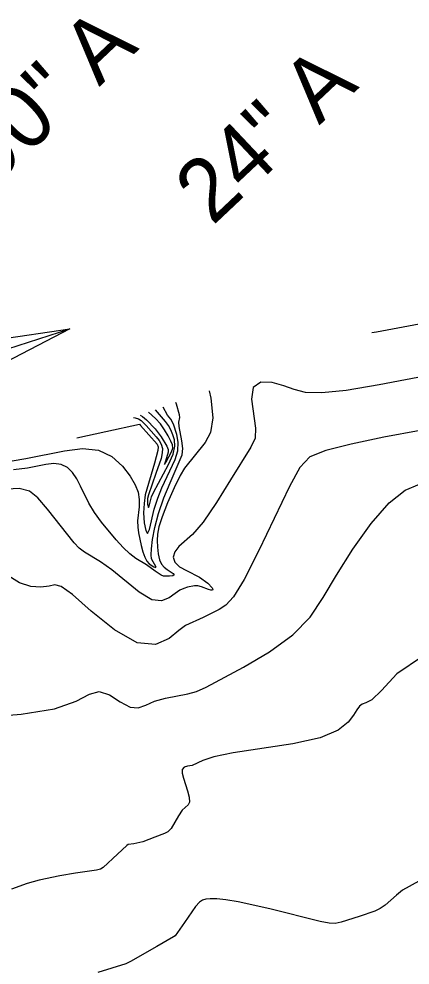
# Model space of a CAD drawing. Extents: x -291892836 to 2945206, y -477993085 to 1832792.
# Drawn here: x 1850179 to 1850412, y 542785 to 543349 of the extents above; entities that cross this region are included whole.
import ezdxf

# ---------------------------------------------------------------- set-up
doc = ezdxf.new("R2010")
doc.units = 0
for name, color, linetype in [('DT_X_Contour_Minor', 7, 'Continuous'), ('Level 31', 7, 'Continuous'), ('Level 40', 7, 'Continuous')]:
    doc.layers.add(name, color=color, linetype=linetype)

msp = doc.modelspace()

# ---------------------------------------------------------------- linework, layer by layer
at = {"layer": 'DT_X_Contour_Minor'}
for points in [[(1850427.18, 543169.02), (1850392.15, 543162.56), (1850389.23, 543162.21)], [(1850445.07, 543140.85), (1850393.64, 543131.12), (1850374.1, 543127.86), (1850359.47, 543126.3), (1850349.69, 543126.66), (1850342.92, 543128.37), (1850336.84, 543130.62), (1850329.84, 543132.51), (1850323.13, 543132.68), (1850318.62, 543129.65), (1850317.59, 543122.63), (1850319.94, 543105.28), (1850319.65, 543099.36), (1850317.22, 543093.98), (1850305.11, 543074.54), (1850296.68, 543061.09), (1850288.66, 543049.35), (1850282.28, 543041.87), (1850274.11, 543034.76), (1850271.79, 543031.72), (1850270.86, 543028.49), (1850271.76, 543025.41), (1850274.64, 543022.77), (1850278.72, 543020.49), (1850286.49, 543016.5), (1850291.44, 543013), (1850294.13, 543010.26), (1850294.55, 543009.35), (1850294.28, 543008.85), (1850293.38, 543008.77), (1850291.92, 543009.14), (1850287.81, 543010.77), (1850285.57, 543011.36), (1850283.45, 543011.43), (1850279.37, 543010.5), (1850277.23, 543009.81), (1850274.82, 543008.73), (1850271.98, 543006.88), (1850268.48, 543004.25), (1850263.96, 543002.34), (1850258.02, 543003.03), (1850250.51, 543007.51), (1850234.29, 543020.88), (1850227.54, 543025.76), (1850217.92, 543031.5), (1850214.75, 543033.83), (1850211.71, 543036.97), (1850195.83, 543057.07), (1850190.01, 543063.83), (1850185.21, 543067.84), (1850178.99, 543069.27), (1850168.18, 543068.71)], [(1850292.22, 543127.66), (1850293.2, 543123.26), (1850294.43, 543111.39), (1850293.06, 543102.7), (1850290, 543096.81), (1850277.59, 543081.54), (1850275, 543077.11), (1850271.42, 543069.68), (1850267.54, 543060.78), (1850264.26, 543052.52), (1850262.28, 543046.5), (1850261.39, 543042.15), (1850261.22, 543038.4), (1850261.41, 543034.4), (1850261.92, 543030.42), (1850262.76, 543026.94), (1850263.93, 543024.35), (1850265.42, 543022.49), (1850267.24, 543021.06), (1850270.91, 543018.8), (1850271.49, 543017.98), (1850270.58, 543017.4), (1850268.72, 543017.07), (1850265.1, 543017.14), (1850263.74, 543017.65), (1850260.15, 543020.18), (1850254.86, 543023.93), (1850248.62, 543027.7), (1850245.03, 543030.39), (1850241.06, 543034.11), (1850236.8, 543038.71), (1850228.02, 543049.4), (1850223.94, 543055.02), (1850220.45, 543060.55), (1850215.47, 543070.71), (1850213.27, 543075.14), (1850210.75, 543078.98), (1850207.74, 543081.96), (1850204.08, 543083.75), (1850199.72, 543084.18), (1850194.82, 543083.62), (1850183.92, 543081.47), (1850175.52, 543080.51)], [(1850174.9, 543085.88), (1850182.88, 543087.18), (1850205.98, 543091.89), (1850216.71, 543093.11), (1850226.28, 543092.17), (1850234.23, 543088.37), (1850240.52, 543082.77), (1850245.16, 543076.81), (1850248.23, 543071.64), (1850249.95, 543067.15), (1850250.61, 543062.87), (1850250.5, 543058.49), (1850249.65, 543050.06), (1850249.68, 543046.41), (1850250.11, 543042.95), (1850251.67, 543035.48), (1850252.68, 543031.64), (1850253.86, 543028.37), (1850255.18, 543026.02), (1850256.6, 543024.47), (1850259.37, 543022.65), (1850260.36, 543022.27), (1850260.72, 543022.4), (1850257.86, 543027.45), (1850257.68, 543029.79), (1850257.9, 543033.46), (1850258.56, 543038.96), (1850259.88, 543046.09), (1850262.1, 543054.52), (1850265.32, 543063.76), (1850268.97, 543072.74), (1850276.17, 543089.46), (1850276.56, 543093.21), (1850276.05, 543097.72), (1850274.39, 543106.35), (1850274.27, 543108.89), (1850274.76, 543111.7), (1850274.62, 543113.34), (1850272.72, 543119.7), (1850272.44, 543120.62)], [(1850213.41, 543099.59), (1850230.58, 543103.35), (1850250.72, 543107.62), (1850251.41, 543106.93), (1850261.27, 543095.78), (1850261.84, 543094.21), (1850261.67, 543092.03), (1850259.78, 543084.52), (1850254.21, 543065.59), (1850253.43, 543060.52), (1850253.15, 543054.84), (1850253.56, 543048.94), (1850254.47, 543044.28), (1850255.58, 543042.59), (1850256.7, 543045.03), (1850259.52, 543057.14), (1850261.59, 543063.67), (1850264.07, 543069.83), (1850272.09, 543086.61), (1850273.57, 543091.83), (1850273.75, 543096.89), (1850273.02, 543101.47), (1850271.01, 543107.79), (1850269.41, 543110.66), (1850267.4, 543113.14), (1850264.88, 543117.92)], [(1850247.21, 543111.63), (1850248.13, 543111.5), (1850250.08, 543110.85), (1850251.7, 543109.89), (1850254.81, 543106.91), (1850260.74, 543100.18), (1850262.46, 543097.94), (1850263.73, 543095.69), (1850264.4, 543093.3), (1850264.34, 543090.57), (1850263.6, 543087.29), (1850260.51, 543078.27), (1850256.04, 543065.58), (1850255.55, 543063.41), (1850255.55, 543059.95), (1850256.14, 543058.1), (1850256.46, 543058.81), (1850257.96, 543064.36), (1850259.18, 543067.01), (1850268.06, 543083.57), (1850270.75, 543089.83), (1850271.85, 543094.68), (1850271.65, 543098.35), (1850270.69, 543101.4), (1850269.44, 543104.25), (1850267.97, 543106.93), (1850266.3, 543109.3), (1850260.24, 543116.27)], [(1850251.2, 543113.05), (1850252.5, 543112.3), (1850254.97, 543110.26), (1850260.01, 543104.86), (1850263.65, 543100.09), (1850267.14, 543094.57), (1850267.82, 543092.61), (1850267.76, 543090.94), (1850265.6, 543083.63), (1850266.72, 543085.18), (1850269.86, 543091.17), (1850270.53, 543093.45), (1850270.35, 543095.35), (1850269.43, 543097.6), (1850267.86, 543100.72), (1850265.74, 543104.36), (1850263.19, 543107.94), (1850260.35, 543111), (1850256.15, 543114.81)], [(1850418.06, 543104.03), (1850396.56, 543099.9), (1850377, 543095.86), (1850361.79, 543092.05), (1850352.38, 543088.14), (1850346.34, 543081.87), (1850340.28, 543070.53), (1850321.96, 543032.49), (1850313.13, 543015.2), (1850306.82, 543004.84), (1850302.28, 542999.86), (1850298.17, 542997.34), (1850288.64, 542992.47), (1850278.1, 542987.64), (1850274.18, 542984.71), (1850268.37, 542980.02), (1850260.19, 542976.36), (1850249.27, 542977.32), (1850235.77, 542985.09), (1850221.99, 542996.28), (1850210.74, 543006.12), (1850203.99, 543011.01), (1850200.15, 543011.97), (1850196.78, 543011.17), (1850191.95, 543010.54), (1850185.86, 543010.97), (1850179.25, 543013.09), (1850172.72, 543017.2)], [(1850157.69, 542933.19), (1850180.09, 542934.85), (1850200.01, 542938.01), (1850213.06, 542942.56), (1850220.88, 542946.76), (1850226.62, 542948.47), (1850232.78, 542946.34), (1850239.21, 542942.29), (1850245.11, 542939.04), (1850249.97, 542938.65), (1850254.49, 542940.33), (1850259.69, 542942.66), (1850266.21, 542944.47), (1850279.62, 542946.99), (1850284.79, 542948.47), (1850290.58, 542951.05), (1850312.81, 542962.79), (1850328.25, 542971.93), (1850342.29, 542982.14), (1850352.48, 542992.77), (1850360.28, 543004.36), (1850368.15, 543017.75), (1850377.91, 543033.16), (1850388.85, 543048.43), (1850399.63, 543060.8), (1850409.23, 543068.28), (1850417.77, 543071.99)], [(1850419.6, 542969.26), (1850404.25, 542958.92), (1850395.02, 542949), (1850389.26, 542943.52), (1850385.75, 542941.54), (1850383.58, 542940.88), (1850381.96, 542939.7), (1850380.36, 542937.56), (1850378.36, 542934.32), (1850375.24, 542930.03), (1850369.31, 542925.29), (1850358.57, 542920.86), (1850342.13, 542917.29), (1850306.51, 542911.9), (1850295.12, 542909.49), (1850288.53, 542907.33), (1850282.19, 542904.36), (1850279.33, 542903.88), (1850277.48, 542903.24), (1850276.25, 542901.94), (1850276.14, 542899.77), (1850276.93, 542896.81), (1850279.44, 542889.22), (1850280.36, 542885.44), (1850280.57, 542882.53), (1850279.84, 542880.88), (1850276.29, 542877.71), (1850274.01, 542874.31), (1850269.55, 542866.83), (1850267.64, 542864.83), (1850265.66, 542863.81), (1850259.97, 542861.65), (1850252.78, 542858.81), (1850247.34, 542857.66), (1850244, 542857.17), (1850243.26, 542856.64), (1850237.58, 542851.4)], [(1850237.58, 542851.4), (1850229.09, 542843.52), (1850227.41, 542842.53), (1850225.03, 542841.9), (1850212.48, 542840.06), (1850203.32, 542838.53), (1850190.89, 542835.97), (1850183.8, 542833.89), (1850174.31, 542830.53)], [(1850417.25, 542835.33), (1850407.59, 542829.94), (1850404.1, 542827.09), (1850397.24, 542821), (1850394.26, 542818.99), (1850391.1, 542817.53), (1850381.76, 542814.31), (1850371.05, 542810.95), (1850367.42, 542810.16), (1850363.82, 542810.27), (1850358.44, 542811.37), (1850328.54, 542818.9), (1850309.5, 542823.04), (1850302.26, 542824.23), (1850296.83, 542824.77), (1850292.94, 542824.83), (1850290.23, 542824.58), (1850288.28, 542824.08), (1850286.49, 542822.83), (1850284.2, 542820.17), (1850277.54, 542810.76), (1850271.98, 542802.81), (1850271.01, 542802.13), (1850261.17, 542796.41), (1850245.42, 542787.4), (1850242.5, 542786.15), (1850225.96, 542780.97)]]:
    msp.add_lwpolyline(points, dxfattribs=at)
at = {"layer": 'Level 31'}
for p, q in [((1850157.4, 543156.8), (1850209.11, 543164.49)), ((1850158.73, 543148.19), (1850209.11, 543164.49)), ((1850209.11, 543164.49), (1850162.68, 543140.46))]:
    msp.add_line(p, q, dxfattribs=at)

# ---------------------------------------------------------------- texts
at = {"layer": 'Level 40'}
for s, p in [('90" A', (1850163.04, 543248.5)), ('24" A', (1850294.29, 543225.55))]:
    msp.add_text(s, height=37.5, rotation=43.3446, dxfattribs=at).set_placement(p)

doc.saveas('drawing.dxf')
